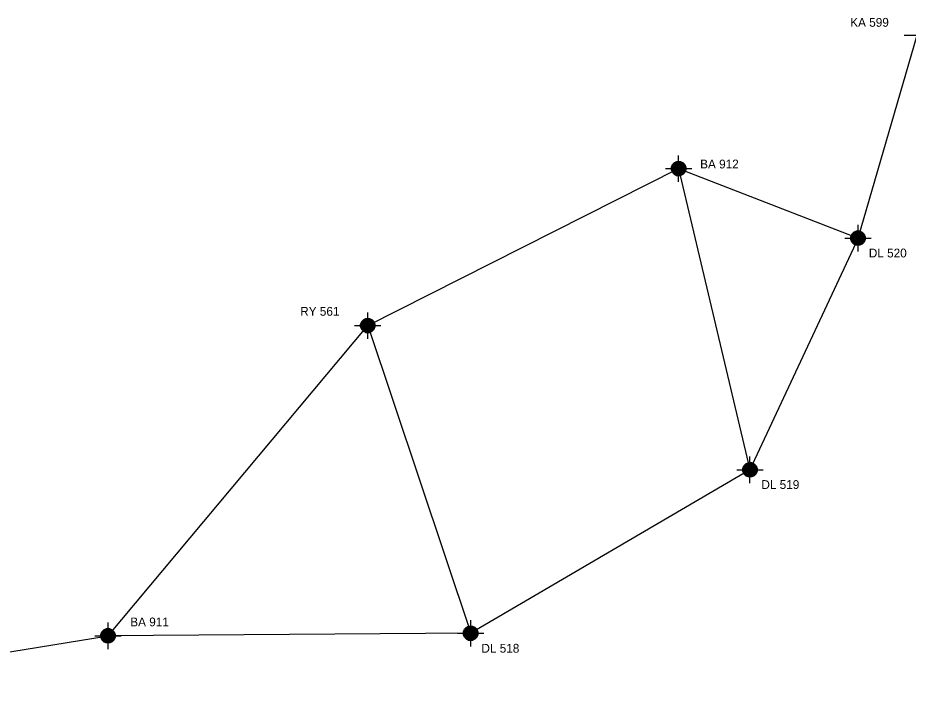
# Model space of a CAD drawing. Extents: x -346533 to -339969, y -1273090 to -1271585.
# Drawn here: x -343494 to -342735, y -1272647 to -1272074 of the extents above; entities that cross this region are included whole.
import ezdxf

# ---------------------------------------------------------------- set-up
doc = ezdxf.new("R2010")
doc.units = 0
for name, color, linetype in [('BP_11', 7, 'Continuous'), ('BP_12', 7, 'Continuous'), ('BP_14', 7, 'Continuous')]:
    doc.layers.add(name, color=color, linetype=linetype)

msp = doc.modelspace()

# ---------------------------------------------------------------- linework, layer by layer
at = {"layer": 'BP_11'}
for points in [[(-342738.84, -1272088.85), (-342732.49, -1272088.85), (-342726.14, -1272088.85), (-342719.79, -1272088.85), (-342716.34, -1272088.85)], [(-342930.99, -1272213.65), (-342930.99, -1272207.3), (-342930.99, -1272200.95), (-342930.99, -1272194.6), (-342930.99, -1272191.15)], [(-342930.99, -1272196.25), (-342929.79, -1272196.25), (-342927.54, -1272197.2), (-342925.84, -1272198.9), (-342924.89, -1272201.15), (-342924.89, -1272203.6), (-342925.84, -1272205.85), (-342927.54, -1272207.55), (-342929.79, -1272208.5), (-342932.24, -1272208.5), (-342934.49, -1272207.55), (-342936.19, -1272205.85), (-342937.14, -1272203.6), (-342937.14, -1272201.15), (-342936.19, -1272198.9), (-342934.49, -1272197.2), (-342932.24, -1272196.25), (-342931.04, -1272196.25), (-342929.24, -1272196.6), (-342932.84, -1272196.6), (-342933.64, -1272197), (-342928.44, -1272197), (-342927.64, -1272197.4), (-342933.99, -1272197.4), (-342934.44, -1272197.4), (-342934.84, -1272197.8), (-342928.49, -1272197.8), (-342927.24, -1272197.8), (-342926.84, -1272198.2), (-342933.19, -1272198.2), (-342935.24, -1272198.2), (-342935.64, -1272198.6), (-342929.29, -1272198.6), (-342926.44, -1272198.6), (-342926.04, -1272199), (-342932.39, -1272199), (-342936.04, -1272199), (-342936.04, -1272199.4), (-342929.69, -1272199.4), (-342926.04, -1272199.4), (-342925.64, -1272199.8), (-342931.99, -1272199.8), (-342936.44, -1272199.8), (-342936.44, -1272200.2), (-342930.09, -1272200.2), (-342925.64, -1272200.2), (-342925.24, -1272200.6), (-342931.59, -1272200.6), (-342936.84, -1272200.6), (-342936.84, -1272201), (-342930.49, -1272201), (-342925.24, -1272201), (-342925.24, -1272201.4), (-342931.59, -1272201.4), (-342936.84, -1272201.4), (-342936.84, -1272201.8), (-342930.49, -1272201.8), (-342925.24, -1272201.8), (-342925.24, -1272202.2), (-342931.59, -1272202.2), (-342936.84, -1272202.2), (-342936.84, -1272202.6), (-342930.49, -1272202.6), (-342925.24, -1272202.6), (-342925.24, -1272203), (-342931.59, -1272203), (-342936.84, -1272203), (-342936.84, -1272203.4), (-342930.49, -1272203.4), (-342925.24, -1272203.4), (-342925.24, -1272203.8), (-342931.59, -1272203.8), (-342936.84, -1272203.8), (-342936.84, -1272204.2), (-342930.49, -1272204.2), (-342925.24, -1272204.2), (-342925.64, -1272204.6), (-342931.99, -1272204.6), (-342936.44, -1272204.6), (-342936.44, -1272205), (-342930.09, -1272205), (-342925.64, -1272205), (-342926.04, -1272205.4), (-342932.39, -1272205.4), (-342936.04, -1272205.4), (-342936.04, -1272205.8), (-342929.69, -1272205.8), (-342926.04, -1272205.8), (-342926.44, -1272206.2), (-342932.79, -1272206.2), (-342935.64, -1272206.2), (-342935.24, -1272206.6), (-342928.89, -1272206.6), (-342926.84, -1272206.6), (-342927.24, -1272207), (-342933.59, -1272207), (-342934.84, -1272207), (-342934.44, -1272207.4), (-342928.09, -1272207.4), (-342927.64, -1272207.4)], [(-342942.24, -1272202.4), (-342935.89, -1272202.4), (-342929.54, -1272202.4), (-342923.19, -1272202.4), (-342919.74, -1272202.4)], [(-342927.64, -1272207.4), (-342928.44, -1272207.8), (-342933.64, -1272207.8), (-342932.84, -1272208.2), (-342929.24, -1272208.2)], [(-342778.11, -1272272.92), (-342778.11, -1272266.57), (-342778.11, -1272260.22), (-342778.11, -1272253.87), (-342778.11, -1272250.42)], [(-342778.11, -1272255.52), (-342776.91, -1272255.52), (-342774.66, -1272256.47), (-342772.96, -1272258.17), (-342772.01, -1272260.42), (-342772.01, -1272262.87), (-342772.96, -1272265.12), (-342774.66, -1272266.82), (-342776.91, -1272267.77), (-342779.36, -1272267.77), (-342781.61, -1272266.82), (-342783.31, -1272265.12), (-342784.26, -1272262.87), (-342784.26, -1272260.42), (-342783.31, -1272258.17), (-342781.61, -1272256.47), (-342779.36, -1272255.52), (-342778.16, -1272255.52), (-342776.36, -1272255.87), (-342779.96, -1272255.87), (-342780.76, -1272256.27), (-342775.56, -1272256.27), (-342774.76, -1272256.67), (-342781.11, -1272256.67), (-342781.56, -1272256.67), (-342781.96, -1272257.07), (-342775.61, -1272257.07), (-342774.36, -1272257.07), (-342773.96, -1272257.47), (-342780.31, -1272257.47), (-342782.36, -1272257.47), (-342782.76, -1272257.87), (-342776.41, -1272257.87), (-342773.56, -1272257.87), (-342773.16, -1272258.27), (-342779.51, -1272258.27), (-342783.16, -1272258.27), (-342783.16, -1272258.67), (-342776.81, -1272258.67), (-342773.16, -1272258.67), (-342772.76, -1272259.07), (-342779.11, -1272259.07), (-342783.56, -1272259.07), (-342783.56, -1272259.47), (-342777.21, -1272259.47), (-342772.76, -1272259.47), (-342772.36, -1272259.87), (-342778.71, -1272259.87), (-342783.96, -1272259.87), (-342783.96, -1272260.27), (-342777.61, -1272260.27), (-342772.36, -1272260.27), (-342772.36, -1272260.67), (-342778.71, -1272260.67), (-342783.96, -1272260.67), (-342783.96, -1272261.07), (-342777.61, -1272261.07), (-342772.36, -1272261.07), (-342772.36, -1272261.47), (-342778.71, -1272261.47), (-342783.96, -1272261.47), (-342783.96, -1272261.87), (-342777.61, -1272261.87), (-342772.36, -1272261.87), (-342772.36, -1272262.27), (-342778.71, -1272262.27), (-342783.96, -1272262.27), (-342783.96, -1272262.67), (-342777.61, -1272262.67), (-342772.36, -1272262.67), (-342772.36, -1272263.07), (-342778.71, -1272263.07), (-342783.96, -1272263.07), (-342783.96, -1272263.47), (-342777.61, -1272263.47), (-342772.36, -1272263.47), (-342772.76, -1272263.87), (-342779.11, -1272263.87), (-342783.56, -1272263.87), (-342783.56, -1272264.27), (-342777.21, -1272264.27), (-342772.76, -1272264.27), (-342773.16, -1272264.67), (-342779.51, -1272264.67), (-342783.16, -1272264.67), (-342783.16, -1272265.07), (-342776.81, -1272265.07), (-342773.16, -1272265.07), (-342773.56, -1272265.47), (-342779.91, -1272265.47), (-342782.76, -1272265.47), (-342782.36, -1272265.87), (-342776.01, -1272265.87), (-342773.96, -1272265.87), (-342774.36, -1272266.27), (-342780.71, -1272266.27), (-342781.96, -1272266.27), (-342781.56, -1272266.67), (-342775.21, -1272266.67), (-342774.76, -1272266.67)], [(-342789.36, -1272261.67), (-342783.01, -1272261.67), (-342776.66, -1272261.67), (-342770.31, -1272261.67), (-342766.86, -1272261.67)], [(-342774.76, -1272266.67), (-342775.56, -1272267.07), (-342780.76, -1272267.07), (-342779.96, -1272267.47), (-342776.36, -1272267.47)], [(-343195.92, -1272347.37), (-343195.92, -1272341.02), (-343195.92, -1272334.67), (-343195.92, -1272328.32), (-343195.92, -1272324.87)], [(-343207.17, -1272336.12), (-343200.82, -1272336.12), (-343194.47, -1272336.12), (-343188.12, -1272336.12), (-343184.67, -1272336.12)], [(-343195.92, -1272329.97), (-343194.72, -1272329.97), (-343192.47, -1272330.92), (-343190.77, -1272332.62), (-343189.82, -1272334.87), (-343189.82, -1272337.32), (-343190.77, -1272339.57), (-343192.47, -1272341.27), (-343194.72, -1272342.22), (-343197.17, -1272342.22), (-343199.42, -1272341.27), (-343201.12, -1272339.57), (-343202.07, -1272337.32), (-343202.07, -1272334.87), (-343201.12, -1272332.62), (-343199.42, -1272330.92), (-343197.17, -1272329.97), (-343195.97, -1272329.97), (-343194.17, -1272330.32), (-343197.77, -1272330.32), (-343198.57, -1272330.72), (-343193.37, -1272330.72), (-343192.57, -1272331.12), (-343198.92, -1272331.12), (-343199.37, -1272331.12), (-343199.77, -1272331.52), (-343193.42, -1272331.52), (-343192.17, -1272331.52), (-343191.77, -1272331.92), (-343198.12, -1272331.92), (-343200.17, -1272331.92), (-343200.57, -1272332.32), (-343194.22, -1272332.32), (-343191.37, -1272332.32), (-343190.97, -1272332.72), (-343197.32, -1272332.72), (-343200.97, -1272332.72), (-343200.97, -1272333.12), (-343194.62, -1272333.12), (-343190.97, -1272333.12), (-343190.57, -1272333.52), (-343196.92, -1272333.52), (-343201.37, -1272333.52), (-343201.37, -1272333.92), (-343195.02, -1272333.92), (-343190.57, -1272333.92), (-343190.17, -1272334.32), (-343196.52, -1272334.32), (-343201.77, -1272334.32), (-343201.77, -1272334.72), (-343195.42, -1272334.72), (-343190.17, -1272334.72), (-343190.17, -1272335.12), (-343196.52, -1272335.12), (-343201.77, -1272335.12), (-343201.77, -1272335.52), (-343195.42, -1272335.52), (-343190.17, -1272335.52), (-343190.17, -1272335.92), (-343196.52, -1272335.92), (-343201.77, -1272335.92), (-343201.77, -1272336.32), (-343195.42, -1272336.32), (-343190.17, -1272336.32), (-343190.17, -1272336.72), (-343196.52, -1272336.72), (-343201.77, -1272336.72), (-343201.77, -1272337.12), (-343195.42, -1272337.12), (-343190.17, -1272337.12), (-343190.17, -1272337.52), (-343196.52, -1272337.52), (-343201.77, -1272337.52), (-343201.77, -1272337.92), (-343195.42, -1272337.92), (-343190.17, -1272337.92), (-343190.57, -1272338.32), (-343196.92, -1272338.32), (-343201.37, -1272338.32), (-343201.37, -1272338.72), (-343195.02, -1272338.72), (-343190.57, -1272338.72), (-343190.97, -1272339.12), (-343197.32, -1272339.12), (-343200.97, -1272339.12), (-343200.97, -1272339.52), (-343194.62, -1272339.52), (-343190.97, -1272339.52), (-343191.37, -1272339.92), (-343197.72, -1272339.92), (-343200.57, -1272339.92), (-343200.17, -1272340.32), (-343193.82, -1272340.32), (-343191.77, -1272340.32), (-343192.17, -1272340.72), (-343198.52, -1272340.72), (-343199.77, -1272340.72), (-343199.37, -1272341.12), (-343193.02, -1272341.12), (-343192.57, -1272341.12)], [(-343192.57, -1272341.12), (-343193.37, -1272341.52), (-343198.57, -1272341.52), (-343197.77, -1272341.92), (-343194.17, -1272341.92)], [(-342870.21, -1272470.27), (-342870.21, -1272463.92), (-342870.21, -1272457.57), (-342870.21, -1272451.22), (-342870.21, -1272447.77)], [(-342870.21, -1272452.87), (-342869.01, -1272452.87), (-342866.76, -1272453.82), (-342865.06, -1272455.52), (-342864.11, -1272457.77), (-342864.11, -1272460.22), (-342865.06, -1272462.47), (-342866.76, -1272464.17), (-342869.01, -1272465.12), (-342871.46, -1272465.12), (-342873.71, -1272464.17), (-342875.41, -1272462.47), (-342876.36, -1272460.22), (-342876.36, -1272457.77), (-342875.41, -1272455.52), (-342873.71, -1272453.82), (-342871.46, -1272452.87), (-342870.26, -1272452.87), (-342868.46, -1272453.22), (-342872.06, -1272453.22), (-342872.86, -1272453.62), (-342867.66, -1272453.62), (-342866.86, -1272454.02), (-342873.21, -1272454.02), (-342873.66, -1272454.02), (-342874.06, -1272454.42), (-342867.71, -1272454.42), (-342866.46, -1272454.42), (-342866.06, -1272454.82), (-342872.41, -1272454.82), (-342874.46, -1272454.82), (-342874.86, -1272455.22), (-342868.51, -1272455.22), (-342865.66, -1272455.22), (-342865.26, -1272455.62), (-342871.61, -1272455.62), (-342875.26, -1272455.62), (-342875.26, -1272456.02), (-342868.91, -1272456.02), (-342865.26, -1272456.02), (-342864.86, -1272456.42), (-342871.21, -1272456.42), (-342875.66, -1272456.42), (-342875.66, -1272456.82), (-342869.31, -1272456.82), (-342864.86, -1272456.82), (-342864.46, -1272457.22), (-342870.81, -1272457.22), (-342876.06, -1272457.22), (-342876.06, -1272457.62), (-342869.71, -1272457.62), (-342864.46, -1272457.62), (-342864.46, -1272458.02), (-342870.81, -1272458.02), (-342876.06, -1272458.02), (-342876.06, -1272458.42), (-342869.71, -1272458.42), (-342864.46, -1272458.42), (-342864.46, -1272458.82), (-342870.81, -1272458.82), (-342876.06, -1272458.82), (-342876.06, -1272459.22), (-342869.71, -1272459.22), (-342864.46, -1272459.22), (-342864.46, -1272459.62), (-342870.81, -1272459.62), (-342876.06, -1272459.62), (-342876.06, -1272460.02), (-342869.71, -1272460.02), (-342864.46, -1272460.02), (-342864.46, -1272460.42), (-342870.81, -1272460.42), (-342876.06, -1272460.42), (-342876.06, -1272460.82), (-342869.71, -1272460.82), (-342864.46, -1272460.82), (-342864.86, -1272461.22), (-342871.21, -1272461.22), (-342875.66, -1272461.22), (-342875.66, -1272461.62), (-342869.31, -1272461.62), (-342864.86, -1272461.62), (-342865.26, -1272462.02), (-342871.61, -1272462.02), (-342875.26, -1272462.02), (-342875.26, -1272462.42), (-342868.91, -1272462.42), (-342865.26, -1272462.42), (-342865.66, -1272462.82), (-342872.01, -1272462.82), (-342874.86, -1272462.82), (-342874.46, -1272463.22), (-342868.11, -1272463.22), (-342866.06, -1272463.22), (-342866.46, -1272463.62), (-342872.81, -1272463.62), (-342874.06, -1272463.62), (-342873.66, -1272464.02), (-342867.31, -1272464.02), (-342866.86, -1272464.02)], [(-342881.46, -1272459.02), (-342875.11, -1272459.02), (-342868.76, -1272459.02), (-342862.41, -1272459.02), (-342858.96, -1272459.02)], [(-342866.86, -1272464.02), (-342867.66, -1272464.42), (-342872.86, -1272464.42), (-342872.06, -1272464.82), (-342868.46, -1272464.82)], [(-343108.23, -1272609.52), (-343108.23, -1272603.17), (-343108.23, -1272596.82), (-343108.23, -1272590.47), (-343108.23, -1272587.02)], [(-343417.3, -1272594.3), (-343416.1, -1272594.3), (-343413.85, -1272595.25), (-343412.15, -1272596.95), (-343411.2, -1272599.2), (-343411.2, -1272601.65), (-343412.15, -1272603.9), (-343413.85, -1272605.6), (-343416.1, -1272606.55), (-343418.55, -1272606.55), (-343420.8, -1272605.6), (-343422.5, -1272603.9), (-343423.45, -1272601.65), (-343423.45, -1272599.2), (-343422.5, -1272596.95), (-343420.8, -1272595.25), (-343418.55, -1272594.3), (-343417.35, -1272594.3), (-343415.55, -1272594.65), (-343419.15, -1272594.65), (-343419.95, -1272595.05), (-343414.75, -1272595.05), (-343413.95, -1272595.45), (-343420.3, -1272595.45), (-343420.75, -1272595.45), (-343421.15, -1272595.85), (-343414.8, -1272595.85), (-343413.55, -1272595.85), (-343413.15, -1272596.25), (-343419.5, -1272596.25), (-343421.55, -1272596.25), (-343421.95, -1272596.65), (-343415.6, -1272596.65), (-343412.75, -1272596.65), (-343412.35, -1272597.05), (-343418.7, -1272597.05), (-343422.35, -1272597.05), (-343422.35, -1272597.45), (-343416, -1272597.45), (-343412.35, -1272597.45), (-343411.95, -1272597.85), (-343418.3, -1272597.85), (-343422.75, -1272597.85), (-343422.75, -1272598.25), (-343416.4, -1272598.25), (-343411.95, -1272598.25), (-343411.55, -1272598.65), (-343417.9, -1272598.65), (-343423.15, -1272598.65), (-343423.15, -1272599.05), (-343416.8, -1272599.05), (-343411.55, -1272599.05), (-343411.55, -1272599.45), (-343417.9, -1272599.45), (-343423.15, -1272599.45), (-343423.15, -1272599.85), (-343416.8, -1272599.85), (-343411.55, -1272599.85), (-343411.55, -1272600.25), (-343417.9, -1272600.25), (-343423.15, -1272600.25), (-343423.15, -1272600.65), (-343416.8, -1272600.65), (-343411.55, -1272600.65), (-343411.55, -1272601.05), (-343417.9, -1272601.05), (-343423.15, -1272601.05), (-343423.15, -1272601.45), (-343416.8, -1272601.45), (-343411.55, -1272601.45), (-343411.55, -1272601.85), (-343417.9, -1272601.85), (-343423.15, -1272601.85), (-343423.15, -1272602.25), (-343416.8, -1272602.25), (-343411.55, -1272602.25), (-343411.95, -1272602.65), (-343418.3, -1272602.65), (-343422.75, -1272602.65), (-343422.75, -1272603.05), (-343416.4, -1272603.05), (-343411.95, -1272603.05), (-343412.35, -1272603.45), (-343418.7, -1272603.45), (-343422.35, -1272603.45), (-343422.35, -1272603.85), (-343416, -1272603.85), (-343412.35, -1272603.85), (-343412.75, -1272604.25), (-343419.1, -1272604.25), (-343421.95, -1272604.25), (-343421.55, -1272604.65), (-343415.2, -1272604.65), (-343413.15, -1272604.65), (-343413.55, -1272605.05), (-343419.9, -1272605.05), (-343421.15, -1272605.05), (-343420.75, -1272605.45), (-343414.4, -1272605.45), (-343413.95, -1272605.45)], [(-343417.3, -1272611.7), (-343417.3, -1272605.35), (-343417.3, -1272599), (-343417.3, -1272592.65), (-343417.3, -1272589.2)], [(-343108.23, -1272592.12), (-343107.03, -1272592.12), (-343104.78, -1272593.07), (-343103.08, -1272594.77), (-343102.13, -1272597.02), (-343102.13, -1272599.47), (-343103.08, -1272601.72), (-343104.78, -1272603.42), (-343107.03, -1272604.37), (-343109.48, -1272604.37), (-343111.73, -1272603.42), (-343113.43, -1272601.72), (-343114.38, -1272599.47), (-343114.38, -1272597.02), (-343113.43, -1272594.77), (-343111.73, -1272593.07), (-343109.48, -1272592.12), (-343108.28, -1272592.12), (-343106.48, -1272592.47), (-343110.08, -1272592.47), (-343110.88, -1272592.87), (-343105.68, -1272592.87), (-343104.88, -1272593.27), (-343111.23, -1272593.27), (-343111.68, -1272593.27), (-343112.08, -1272593.67), (-343105.73, -1272593.67), (-343104.48, -1272593.67), (-343104.08, -1272594.07), (-343110.43, -1272594.07), (-343112.48, -1272594.07), (-343112.88, -1272594.47), (-343106.53, -1272594.47), (-343103.68, -1272594.47), (-343103.28, -1272594.87), (-343109.63, -1272594.87), (-343113.28, -1272594.87), (-343113.28, -1272595.27), (-343106.93, -1272595.27), (-343103.28, -1272595.27), (-343102.88, -1272595.67), (-343109.23, -1272595.67), (-343113.68, -1272595.67), (-343113.68, -1272596.07), (-343107.33, -1272596.07), (-343102.88, -1272596.07), (-343102.48, -1272596.47), (-343108.83, -1272596.47), (-343114.08, -1272596.47), (-343114.08, -1272596.87), (-343107.73, -1272596.87), (-343102.48, -1272596.87), (-343102.48, -1272597.27), (-343108.83, -1272597.27), (-343114.08, -1272597.27), (-343114.08, -1272597.67), (-343107.73, -1272597.67), (-343102.48, -1272597.67), (-343102.48, -1272598.07), (-343108.83, -1272598.07), (-343114.08, -1272598.07), (-343114.08, -1272598.47), (-343107.73, -1272598.47), (-343102.48, -1272598.47), (-343102.48, -1272598.87), (-343108.83, -1272598.87), (-343114.08, -1272598.87), (-343114.08, -1272599.27), (-343107.73, -1272599.27), (-343102.48, -1272599.27), (-343102.48, -1272599.67), (-343108.83, -1272599.67), (-343114.08, -1272599.67), (-343114.08, -1272600.07), (-343107.73, -1272600.07), (-343102.48, -1272600.07), (-343102.88, -1272600.47), (-343109.23, -1272600.47), (-343113.68, -1272600.47), (-343113.68, -1272600.87), (-343107.33, -1272600.87), (-343102.88, -1272600.87), (-343103.28, -1272601.27), (-343109.63, -1272601.27), (-343113.28, -1272601.27), (-343113.28, -1272601.67), (-343106.93, -1272601.67), (-343103.28, -1272601.67), (-343103.68, -1272602.07), (-343110.03, -1272602.07), (-343112.88, -1272602.07), (-343112.48, -1272602.47), (-343106.13, -1272602.47), (-343104.08, -1272602.47), (-343104.48, -1272602.87), (-343110.83, -1272602.87), (-343112.08, -1272602.87), (-343111.68, -1272603.27), (-343105.33, -1272603.27), (-343104.88, -1272603.27)], [(-343428.55, -1272600.45), (-343422.2, -1272600.45), (-343415.85, -1272600.45), (-343409.5, -1272600.45), (-343406.05, -1272600.45)], [(-343119.48, -1272598.27), (-343113.13, -1272598.27), (-343106.78, -1272598.27), (-343100.43, -1272598.27), (-343096.98, -1272598.27)], [(-343413.95, -1272605.45), (-343414.75, -1272605.85), (-343419.95, -1272605.85), (-343419.15, -1272606.25), (-343415.55, -1272606.25)], [(-343104.88, -1272603.27), (-343105.68, -1272603.67), (-343110.88, -1272603.67), (-343110.08, -1272604.07), (-343106.48, -1272604.07)]]:
    msp.add_lwpolyline(points, dxfattribs=at)
for points in [[(-342929.79, -1272196.25), (-342927.54, -1272197.2), (-342925.84, -1272198.9), (-342924.89, -1272201.15), (-342924.89, -1272203.6), (-342925.84, -1272205.85), (-342927.54, -1272207.55), (-342929.79, -1272208.5), (-342932.24, -1272208.5), (-342934.49, -1272207.55), (-342936.19, -1272205.85), (-342937.14, -1272203.6), (-342937.14, -1272201.15), (-342936.19, -1272198.9), (-342934.49, -1272197.2), (-342932.24, -1272196.25)], [(-342776.91, -1272255.52), (-342774.66, -1272256.47), (-342772.96, -1272258.17), (-342772.01, -1272260.42), (-342772.01, -1272262.87), (-342772.96, -1272265.12), (-342774.66, -1272266.82), (-342776.91, -1272267.77), (-342779.36, -1272267.77), (-342781.61, -1272266.82), (-342783.31, -1272265.12), (-342784.26, -1272262.87), (-342784.26, -1272260.42), (-342783.31, -1272258.17), (-342781.61, -1272256.47), (-342779.36, -1272255.52)], [(-343194.72, -1272329.97), (-343192.47, -1272330.92), (-343190.77, -1272332.62), (-343189.82, -1272334.87), (-343189.82, -1272337.32), (-343190.77, -1272339.57), (-343192.47, -1272341.27), (-343194.72, -1272342.22), (-343197.17, -1272342.22), (-343199.42, -1272341.27), (-343201.12, -1272339.57), (-343202.07, -1272337.32), (-343202.07, -1272334.87), (-343201.12, -1272332.62), (-343199.42, -1272330.92), (-343197.17, -1272329.97)], [(-342869.01, -1272452.87), (-342866.76, -1272453.82), (-342865.06, -1272455.52), (-342864.11, -1272457.77), (-342864.11, -1272460.22), (-342865.06, -1272462.47), (-342866.76, -1272464.17), (-342869.01, -1272465.12), (-342871.46, -1272465.12), (-342873.71, -1272464.17), (-342875.41, -1272462.47), (-342876.36, -1272460.22), (-342876.36, -1272457.77), (-342875.41, -1272455.52), (-342873.71, -1272453.82), (-342871.46, -1272452.87)], [(-343416.1, -1272594.3), (-343413.85, -1272595.25), (-343412.15, -1272596.95), (-343411.2, -1272599.2), (-343411.2, -1272601.65), (-343412.15, -1272603.9), (-343413.85, -1272605.6), (-343416.1, -1272606.55), (-343418.55, -1272606.55), (-343420.8, -1272605.6), (-343422.5, -1272603.9), (-343423.45, -1272601.65), (-343423.45, -1272599.2), (-343422.5, -1272596.95), (-343420.8, -1272595.25), (-343418.55, -1272594.3)], [(-343107.03, -1272592.12), (-343104.78, -1272593.07), (-343103.08, -1272594.77), (-343102.13, -1272597.02), (-343102.13, -1272599.47), (-343103.08, -1272601.72), (-343104.78, -1272603.42), (-343107.03, -1272604.37), (-343109.48, -1272604.37), (-343111.73, -1272603.42), (-343113.43, -1272601.72), (-343114.38, -1272599.47), (-343114.38, -1272597.02), (-343113.43, -1272594.77), (-343111.73, -1272593.07), (-343109.48, -1272592.12)]]:
    msp.add_lwpolyline(points, close=True, dxfattribs=at)
at = {"layer": 'BP_14'}
for p, q in [((-342778.11, -1272261.67), (-342727.59, -1272088.85)), ((-343195.92, -1272336.12), (-342930.99, -1272202.4)), ((-342930.99, -1272202.4), (-342778.11, -1272261.67)), ((-342930.99, -1272202.4), (-342870.21, -1272459.02)), ((-342778.11, -1272261.67), (-342870.21, -1272459.02)), ((-343417.3, -1272600.45), (-343195.92, -1272336.12)), ((-343195.92, -1272336.12), (-343108.23, -1272598.27)), ((-342870.21, -1272459.02), (-343108.23, -1272598.27)), ((-343702.54, -1272646.75), (-343417.3, -1272600.45)), ((-343108.23, -1272598.27), (-343417.3, -1272600.45))]:
    msp.add_line(p, q, dxfattribs=at)

# ---------------------------------------------------------------- texts
at = {"layer": 'BP_12'}
for s, p in [('KA 599', (-342784.74, -1272081.57)), ('BA 912', (-342912.68, -1272202.27)), ('DL 520', (-342768.93, -1272278.08)), ('RY 561', (-343253.51, -1272327.76)), ('DL 519', (-342860.48, -1272475.33)), ('BA 911', (-343398.36, -1272592.36)), ('DL 518', (-343099.09, -1272614.8))]:
    msp.add_text(s, height=7.5, dxfattribs=at).set_placement(p)

doc.saveas('drawing.dxf')
